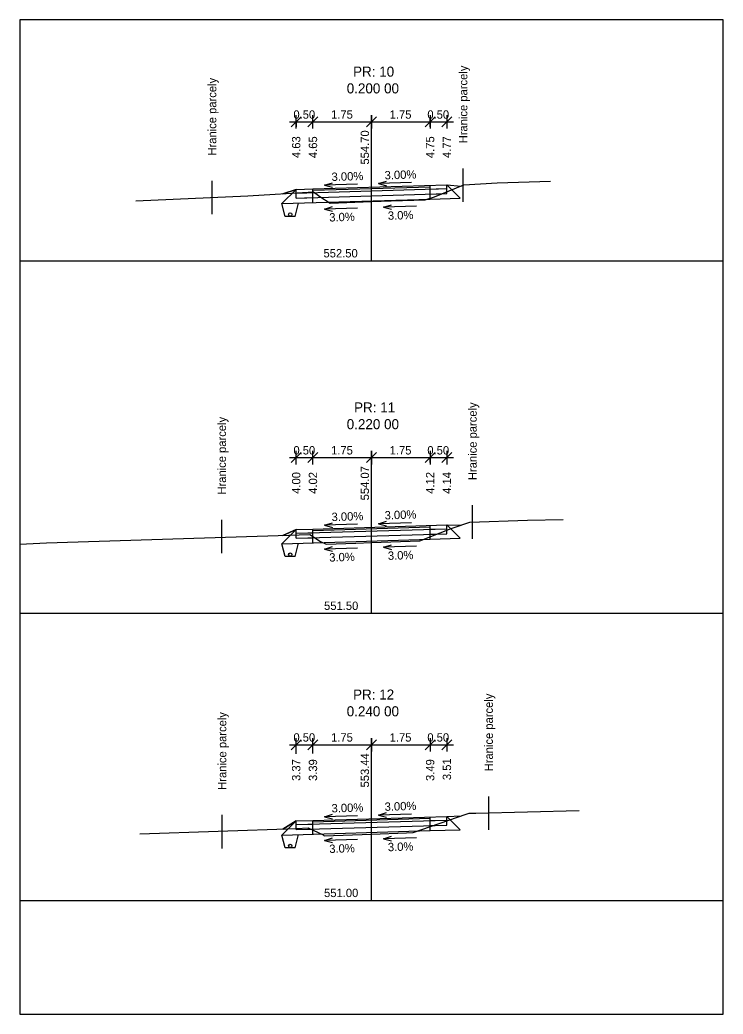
# Model space of a CAD drawing. Extents: x -603737 to -603383, y -1112154 to -1112124.
# Drawn here: x -603636.4 to -603615.4, y -1112153.84 to -1112124.14 of the extents above; entities that cross this region are included whole.
import ezdxf

# ---------------------------------------------------------------- set-up
doc = ezdxf.new("R2010")
doc.units = 0
for name, color, linetype in [('_křivky z hran', 7, 'Continuous'), ('_netisk', 7, 'Continuous'), ('C3D_Podsestava-Popis', 7, 'Continuous'), ('C3D_PP-Popisek', 7, 'Continuous'), ('C3D_PR', 7, 'Continuous'), ('C3D_ZPR', 7, 'Continuous'), ('Default', 7, 'Continuous'), ('konstrukce', 7, 'Continuous')]:
    doc.layers.add(name, color=color, linetype=linetype)

# ---------------------------------------------------------------- blocks, each defined once
blk = doc.blocks.new('_Oblique')
at = {"layer": 'Default'}
blk.add_line((-0.5, -0.5), (0.5, 0.5), dxfattribs=at)
blk = doc.blocks.new('AeccTickLine')
at = {"layer": 'Default'}
blk.add_line((0, 1), (0, -1), dxfattribs=at)

msp = doc.modelspace()

# ---------------------------------------------------------------- linework, layer by layer
at = {"layer": '_netisk'}
msp.add_lwpolyline([(-603636.395, -1112153.84), (-603615.395, -1112153.84), (-603615.395, -1112124.14), (-603636.395, -1112124.14)], close=True, dxfattribs=at)
at = {"layer": 'C3D_Podsestava-Popis'}
for p, q in [((-603628.345, -1112127.186), (-603625.895, -1112127.186)), ((-603627.645, -1112127.336), (-603627.645, -1112127.191)), ((-603625.895, -1112127.336), (-603625.895, -1112127.138)), ((-603625.895, -1112127.186), (-603623.445, -1112127.186)), ((-603624.145, -1112127.336), (-603624.145, -1112127.086)), ((-603623.645, -1112127.071), (-603623.645, -1112127.336)), ((-603628.145, -1112127.206), (-603628.145, -1112127.336)), ((-603628.345, -1112137.217), (-603625.895, -1112137.217)), ((-603625.895, -1112137.217), (-603623.445, -1112137.217)), ((-603624.145, -1112137.367), (-603624.145, -1112137.244)), ((-603623.645, -1112137.229), (-603623.645, -1112137.367)), ((-603628.145, -1112137.364), (-603628.145, -1112137.367)), ((-603627.645, -1112137.367), (-603627.645, -1112137.349)), ((-603625.895, -1112137.367), (-603625.895, -1112137.297)), ((-603628.345, -1112145.794), (-603625.895, -1112145.794)), ((-603625.895, -1112145.794), (-603623.445, -1112145.794)), ((-603628.145, -1112146.069), (-603628.145, -1112145.944)), ((-603627.645, -1112146.054), (-603627.645, -1112145.944)), ((-603625.895, -1112146.001), (-603625.895, -1112145.944)), ((-603624.145, -1112145.949), (-603624.145, -1112145.944)), ((-603623.645, -1112145.934), (-603623.645, -1112145.944))]:
    msp.add_line(p, q, dxfattribs=at)
at = {"layer": 'C3D_PP-Popisek'}
for p, q in [((-603625.687, -1112129.032), (-603625.45, -1112128.956)), ((-603627.298, -1112129.08), (-603627.062, -1112129.005)), ((-603626.314, -1112129.051), (-603627.298, -1112129.08)), ((-603627.298, -1112129.08), (-603627.057, -1112129.141)), ((-603624.703, -1112129.002), (-603625.687, -1112129.032)), ((-603625.687, -1112129.032), (-603625.446, -1112129.093)), ((-603627.298, -1112129.79), (-603627.062, -1112129.715)), ((-603626.314, -1112129.761), (-603627.298, -1112129.79)), ((-603627.298, -1112129.79), (-603627.057, -1112129.851)), ((-603625.534, -1112129.737), (-603625.297, -1112129.662)), ((-603624.55, -1112129.708), (-603625.534, -1112129.737)), ((-603625.534, -1112129.737), (-603625.293, -1112129.799)), ((-603627.298, -1112139.239), (-603627.062, -1112139.163)), ((-603626.314, -1112139.209), (-603627.298, -1112139.239)), ((-603627.298, -1112139.239), (-603627.057, -1112139.3)), ((-603625.687, -1112139.19), (-603625.45, -1112139.115)), ((-603624.703, -1112139.161), (-603625.687, -1112139.19)), ((-603625.687, -1112139.19), (-603625.446, -1112139.251)), ((-603627.298, -1112139.949), (-603627.062, -1112139.873)), ((-603626.314, -1112139.919), (-603627.298, -1112139.949)), ((-603627.298, -1112139.949), (-603627.057, -1112140.01)), ((-603625.534, -1112139.896), (-603625.297, -1112139.82)), ((-603624.55, -1112139.866), (-603625.534, -1112139.896)), ((-603625.534, -1112139.896), (-603625.293, -1112139.957)), ((-603627.298, -1112147.943), (-603627.062, -1112147.868)), ((-603626.314, -1112147.914), (-603627.298, -1112147.943)), ((-603627.298, -1112147.943), (-603627.057, -1112148.004)), ((-603625.687, -1112147.895), (-603625.45, -1112147.819)), ((-603624.703, -1112147.865), (-603625.687, -1112147.895)), ((-603625.687, -1112147.895), (-603625.446, -1112147.956)), ((-603625.534, -1112148.601), (-603625.297, -1112148.525)), ((-603624.55, -1112148.571), (-603625.534, -1112148.601)), ((-603627.298, -1112148.654), (-603627.062, -1112148.578)), ((-603626.314, -1112148.624), (-603627.298, -1112148.654)), ((-603627.298, -1112148.654), (-603627.057, -1112148.715)), ((-603625.534, -1112148.601), (-603625.293, -1112148.662))]:
    msp.add_line(p, q, dxfattribs=at)
at = {"layer": 'C3D_PR'}
for points in [[(-603632.933, -1112129.543), (-603629.584, -1112129.397), (-603627.629, -1112129.279), (-603627.434, -1112129.413), (-603627.125, -1112129.613), (-603625.895, -1112129.57), (-603625.307, -1112129.55), (-603624.296, -1112129.511), (-603624.013, -1112129.422), (-603623.14, -1112129.071), (-603622.14, -1112129.009), (-603620.554, -1112128.961)], [(-603636.395, -1112139.8), (-603635.601, -1112139.765), (-603627.74, -1112139.516), (-603627.415, -1112139.725), (-603627.253, -1112139.802), (-603626.367, -1112139.77), (-603625.895, -1112139.754), (-603624.452, -1112139.705), (-603623.519, -1112139.333), (-603622.96, -1112139.14), (-603621.233, -1112139.089), (-603620.17, -1112139.064)], [(-603632.813, -1112148.457), (-603628.138, -1112148.299), (-603627.79, -1112148.274), (-603627.339, -1112148.489), (-603627.309, -1112148.515), (-603625.895, -1112148.462), (-603624.852, -1112148.424), (-603624.651, -1112148.41), (-603623.065, -1112147.864), (-603622.976, -1112147.833), (-603622.78, -1112147.833), (-603619.689, -1112147.759)]]:
    msp.add_lwpolyline(points, dxfattribs=at)
at = {"layer": 'C3D_ZPR'}
for p, q in [((-603625.895, -1112131.336), (-603625.895, -1112127.336)), ((-603623.157, -1112129.578), (-603623.157, -1112128.578)), ((-603630.655, -1112129.944), (-603630.655, -1112128.944)), ((-603628.568, -1112129.628), (-603628.145, -1112129.206)), ((-603628.145, -1112129.206), (-603628.54, -1112129.334)), ((-603628.54, -1112129.334), (-603628.145, -1112129.206)), ((-603628.145, -1112129.316), (-603623.645, -1112129.181)), ((-603628.145, -1112129.206), (-603627.645, -1112129.191)), ((-603628.145, -1112129.466), (-603628.145, -1112129.206)), ((-603628.145, -1112129.466), (-603628.145, -1112129.206)), ((-603627.645, -1112129.191), (-603623.645, -1112129.071)), ((-603627.645, -1112129.231), (-603624.145, -1112129.126)), ((-603627.645, -1112129.601), (-603627.645, -1112129.191)), ((-603627.645, -1112129.301), (-603627.645, -1112129.231)), ((-603624.145, -1112129.126), (-603624.145, -1112129.086)), ((-603624.145, -1112129.496), (-603624.145, -1112129.086)), ((-603624.145, -1112129.196), (-603623.645, -1112129.181)), ((-603624.145, -1112129.346), (-603624.145, -1112129.196)), ((-603623.645, -1112129.331), (-603623.645, -1112129.071)), ((-603623.645, -1112129.331), (-603623.645, -1112129.071)), ((-603623.645, -1112129.071), (-603623.247, -1112129.469)), ((-603623.645, -1112129.071), (-603623.22, -1112129.103)), ((-603623.645, -1112129.071), (-603623.22, -1112129.103)), ((-603628.568, -1112129.628), (-603624.145, -1112129.496)), ((-603628.145, -1112129.316), (-603627.645, -1112129.301)), ((-603628.145, -1112129.466), (-603623.645, -1112129.331)), ((-603628.145, -1112129.466), (-603627.645, -1112129.451)), ((-603627.645, -1112129.601), (-603627.645, -1112129.451)), ((-603624.145, -1112129.346), (-603623.645, -1112129.331)), ((-603624.145, -1112129.496), (-603623.247, -1112129.469)), ((-603636.395, -1112131.336), (-603615.395, -1112131.336)), ((-603625.895, -1112141.867), (-603625.895, -1112137.367)), ((-603622.878, -1112139.638), (-603622.878, -1112138.638)), ((-603630.365, -1112140.071), (-603630.365, -1112139.071)), ((-603628.568, -1112139.787), (-603628.145, -1112139.364)), ((-603628.145, -1112139.364), (-603628.54, -1112139.541)), ((-603628.54, -1112139.541), (-603628.145, -1112139.364)), ((-603628.145, -1112139.474), (-603623.645, -1112139.339)), ((-603628.145, -1112139.364), (-603627.645, -1112139.349)), ((-603628.145, -1112139.624), (-603628.145, -1112139.364)), ((-603628.145, -1112139.624), (-603628.145, -1112139.364)), ((-603627.645, -1112139.349), (-603623.645, -1112139.229)), ((-603627.645, -1112139.389), (-603624.145, -1112139.284)), ((-603627.645, -1112139.759), (-603627.645, -1112139.349)), ((-603624.145, -1112139.284), (-603624.145, -1112139.244)), ((-603624.145, -1112139.654), (-603624.145, -1112139.244)), ((-603624.145, -1112139.354), (-603623.645, -1112139.339)), ((-603624.145, -1112139.504), (-603624.145, -1112139.354)), ((-603623.645, -1112139.489), (-603623.645, -1112139.229)), ((-603623.645, -1112139.489), (-603623.645, -1112139.229)), ((-603623.645, -1112139.229), (-603623.247, -1112139.627)), ((-603623.645, -1112139.229), (-603623.22, -1112139.23)), ((-603623.645, -1112139.229), (-603623.22, -1112139.23)), ((-603628.568, -1112139.787), (-603624.145, -1112139.654)), ((-603628.145, -1112139.474), (-603627.645, -1112139.459)), ((-603628.145, -1112139.624), (-603623.645, -1112139.489)), ((-603628.145, -1112139.624), (-603627.645, -1112139.609)), ((-603627.645, -1112139.459), (-603627.645, -1112139.389)), ((-603627.645, -1112139.759), (-603627.645, -1112139.609)), ((-603624.145, -1112139.504), (-603623.645, -1112139.489)), ((-603624.145, -1112139.654), (-603623.247, -1112139.627)), ((-603636.395, -1112141.867), (-603615.395, -1112141.867)), ((-603625.895, -1112150.444), (-603625.895, -1112145.944)), ((-603622.395, -1112148.338), (-603622.395, -1112147.338)), ((-603630.356, -1112148.89), (-603630.356, -1112147.89)), ((-603627.645, -1112148.054), (-603623.645, -1112147.934)), ((-603624.145, -1112147.989), (-603624.145, -1112147.949)), ((-603624.145, -1112148.359), (-603624.145, -1112147.949)), ((-603623.645, -1112147.934), (-603623.22, -1112147.917)), ((-603623.645, -1112147.934), (-603623.22, -1112147.917)), ((-603623.645, -1112148.194), (-603623.645, -1112147.934)), ((-603623.645, -1112148.194), (-603623.645, -1112147.934)), ((-603623.247, -1112148.332), (-603623.645, -1112147.934)), ((-603628.568, -1112148.492), (-603628.145, -1112148.069)), ((-603628.145, -1112148.069), (-603628.54, -1112148.313)), ((-603628.54, -1112148.313), (-603628.145, -1112148.069)), ((-603628.145, -1112148.179), (-603623.645, -1112148.044)), ((-603628.145, -1112148.069), (-603627.645, -1112148.054)), ((-603628.145, -1112148.329), (-603628.145, -1112148.069)), ((-603628.145, -1112148.329), (-603628.145, -1112148.069)), ((-603628.145, -1112148.179), (-603627.645, -1112148.164)), ((-603628.145, -1112148.329), (-603623.645, -1112148.194)), ((-603627.645, -1112148.094), (-603624.145, -1112147.989)), ((-603627.645, -1112148.464), (-603627.645, -1112148.054)), ((-603627.645, -1112148.164), (-603627.645, -1112148.094)), ((-603624.145, -1112148.059), (-603623.645, -1112148.044)), ((-603624.145, -1112148.209), (-603624.145, -1112148.059)), ((-603624.145, -1112148.209), (-603623.645, -1112148.194)), ((-603628.568, -1112148.492), (-603624.145, -1112148.359)), ((-603628.145, -1112148.329), (-603627.645, -1112148.314)), ((-603627.645, -1112148.464), (-603627.645, -1112148.314)), ((-603624.145, -1112148.359), (-603623.247, -1112148.332)), ((-603636.395, -1112150.444), (-603615.395, -1112150.444))]:
    msp.add_line(p, q, dxfattribs=at)
at = {"layer": 'konstrukce'}
for p, q in [((-603628.472, -1112130.014), (-603628.568, -1112129.628)), ((-603628.172, -1112130.014), (-603628.072, -1112129.614)), ((-603628.172, -1112130.014), (-603628.472, -1112130.014)), ((-603628.472, -1112140.172), (-603628.568, -1112139.787)), ((-603628.172, -1112140.172), (-603628.072, -1112139.772)), ((-603628.172, -1112140.172), (-603628.472, -1112140.172)), ((-603628.472, -1112148.877), (-603628.568, -1112148.492)), ((-603628.172, -1112148.877), (-603628.072, -1112148.477)), ((-603628.172, -1112148.877), (-603628.472, -1112148.877))]:
    msp.add_line(p, q, dxfattribs=at)
for centre in [(-603628.322, -1112129.954), (-603628.322, -1112140.112), (-603628.322, -1112148.817)]:
    msp.add_circle(centre, 0.05, dxfattribs=at)

# ---------------------------------------------------------------- block references
at = {"layer": '_křivky z hran', "rotation": 180}
for name, p, xscale, yscale in [('_Oblique', (-603628.145, -1112127.186), 0.3, 0.3), ('AeccTickLine', (-603628.145, -1112127.186), 0.2, 0.20000000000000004), ('_Oblique', (-603627.645, -1112127.186), 0.3, 0.3), ('AeccTickLine', (-603627.645, -1112127.186), 0.2, 0.20000000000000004), ('_Oblique', (-603625.895, -1112127.186), 0.3, 0.3), ('AeccTickLine', (-603625.895, -1112127.186), 0.2, 0.20000000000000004), ('_Oblique', (-603628.145, -1112137.217), 0.3, 0.3), ('AeccTickLine', (-603628.145, -1112137.217), 0.2, 0.20000000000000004), ('_Oblique', (-603627.645, -1112137.217), 0.3, 0.3), ('AeccTickLine', (-603627.645, -1112137.217), 0.2, 0.20000000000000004), ('_Oblique', (-603625.895, -1112137.217), 0.3, 0.3), ('AeccTickLine', (-603625.895, -1112137.217), 0.2, 0.20000000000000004), ('AeccTickLine', (-603628.145, -1112145.794), 0.2, 0.20000000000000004), ('AeccTickLine', (-603627.645, -1112145.794), 0.2, 0.20000000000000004), ('AeccTickLine', (-603625.895, -1112145.794), 0.2, 0.20000000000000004), ('_Oblique', (-603628.145, -1112145.794), 0.3, 0.3), ('_Oblique', (-603627.645, -1112145.794), 0.3, 0.3), ('_Oblique', (-603625.895, -1112145.794), 0.3, 0.3)]:
    msp.add_blockref(name, p, dxfattribs=dict(at, xscale=xscale, yscale=yscale))
at = {"layer": '_křivky z hran'}
for name, p, xscale, yscale in [('_Oblique', (-603625.895, -1112127.186), 0.3, 0.3), ('AeccTickLine', (-603625.895, -1112127.186), 0.2, 0.20000000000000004), ('_Oblique', (-603624.145, -1112127.186), 0.3, 0.3), ('AeccTickLine', (-603624.145, -1112127.186), 0.2, 0.20000000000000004), ('_Oblique', (-603623.645, -1112127.186), 0.3, 0.3), ('AeccTickLine', (-603623.645, -1112127.186), 0.2, 0.20000000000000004), ('_Oblique', (-603625.895, -1112137.217), 0.3, 0.3), ('AeccTickLine', (-603625.895, -1112137.217), 0.2, 0.20000000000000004), ('_Oblique', (-603624.145, -1112137.217), 0.3, 0.3), ('AeccTickLine', (-603624.145, -1112137.217), 0.2, 0.20000000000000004), ('_Oblique', (-603623.645, -1112137.217), 0.3, 0.3), ('AeccTickLine', (-603623.645, -1112137.217), 0.2, 0.20000000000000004), ('AeccTickLine', (-603625.895, -1112145.794), 0.2, 0.20000000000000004), ('AeccTickLine', (-603624.145, -1112145.794), 0.2, 0.20000000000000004), ('AeccTickLine', (-603623.645, -1112145.794), 0.2, 0.20000000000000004), ('_Oblique', (-603625.895, -1112145.794), 0.3, 0.3), ('_Oblique', (-603624.145, -1112145.794), 0.3, 0.3), ('_Oblique', (-603623.645, -1112145.794), 0.3, 0.3)]:
    msp.add_blockref(name, p, dxfattribs=dict(at, xscale=xscale, yscale=yscale))

# ---------------------------------------------------------------- texts
at = {"layer": 'C3D_Podsestava-Popis'}
for s, rotation, p in [('0.50', 360, (-603628.227, -1112127.092)), ('1.75', 360, (-603627.103, -1112127.092)), ('1.75', 360, (-603627.103, -1112127.092)), ('1.75', 360, (-603625.353, -1112127.092)), ('1.75', 360, (-603625.353, -1112127.092)), ('0.50', 360, (-603624.227, -1112127.092)), ('554.70', 90, (-603625.969, -1112128.462)), ('4.63', 90, (-603628.019, -1112128.268)), ('4.63', 90, (-603628.019, -1112128.268)), ('4.65', 90, (-603627.519, -1112128.269)), ('4.75', 90, (-603624.02, -1112128.269)), ('4.77', 90, (-603623.52, -1112128.268)), ('4.77', 90, (-603623.52, -1112128.268)), ('3.00%', 1.7184, (-603625.5, -1112128.906)), ('3.00%', 1.7184, (-603627.085, -1112128.954)), ('3.0%', 1.7184, (-603625.403, -1112130.113)), ('3.0%', 1.7184, (-603627.153, -1112130.165)), ('0.50', 360, (-603628.227, -1112137.123)), ('1.75', 360, (-603627.103, -1112137.123)), ('1.75', 360, (-603627.103, -1112137.123)), ('1.75', 360, (-603625.353, -1112137.123)), ('1.75', 360, (-603625.353, -1112137.123)), ('0.50', 360, (-603624.227, -1112137.123)), ('554.07', 90, (-603625.969, -1112138.493)), ('4.00', 90, (-603628.019, -1112138.298)), ('4.00', 90, (-603628.019, -1112138.298)), ('4.02', 90, (-603627.519, -1112138.297)), ('4.12', 90, (-603624.019, -1112138.297)), ('4.14', 90, (-603623.519, -1112138.298)), ('4.14', 90, (-603623.519, -1112138.298)), ('3.00%', 1.7184, (-603627.085, -1112139.113)), ('3.00%', 1.7184, (-603625.5, -1112139.064)), ('3.0%', 1.7184, (-603627.153, -1112140.324)), ('3.0%', 1.7184, (-603625.403, -1112140.271)), ('0.50', 360, (-603628.227, -1112145.7)), ('1.75', 360, (-603627.103, -1112145.7)), ('1.75', 360, (-603627.103, -1112145.7)), ('1.75', 360, (-603625.353, -1112145.7)), ('1.75', 360, (-603625.353, -1112145.7)), ('0.50', 360, (-603624.227, -1112145.7)), ('553.44', 90, (-603625.969, -1112147.069)), ('3.37', 90, (-603628.019, -1112146.875)), ('3.37', 90, (-603628.019, -1112146.875)), ('3.39', 90, (-603627.519, -1112146.876)), ('3.49', 90, (-603624.019, -1112146.876)), ('3.51', 90, (-603623.519, -1112146.851)), ('3.51', 90, (-603623.519, -1112146.851)), ('3.00%', 1.7184, (-603627.085, -1112147.817)), ('3.00%', 1.7184, (-603625.5, -1112147.769)), ('3.0%', 1.7184, (-603627.153, -1112149.028)), ('3.0%', 1.7184, (-603625.403, -1112148.976))]:
    msp.add_text(s, height=0.25, rotation=rotation, dxfattribs=at).set_placement(p)
at = {"layer": 'C3D_ZPR'}
for s, p in [('PR: 10', (-603626.445, -1112125.836)), ('0.200 00', (-603626.635, -1112126.336)), ('PR: 11', (-603626.415, -1112135.867)), ('0.220 00', (-603626.635, -1112136.367)), ('PR: 12', (-603626.445, -1112144.444)), ('0.240 00', (-603626.635, -1112144.944))]:
    msp.add_text(s, height=0.3, dxfattribs=at).set_placement(p)
for s, rotation, p in [('Hranice parcely', 90, (-603623.032, -1112127.828)), ('Hranice parcely', 90, (-603630.53, -1112128.194)), ('552.50', 360, (-603627.329, -1112131.236)), ('Hranice parcely', 90, (-603622.753, -1112137.888)), ('Hranice parcely', 90, (-603630.24, -1112138.321)), ('551.50', 360, (-603627.312, -1112141.767)), ('Hranice parcely', 90, (-603622.27, -1112146.588)), ('Hranice parcely', 90, (-603630.231, -1112147.14)), ('551.00', 360, (-603627.312, -1112150.344))]:
    msp.add_text(s, height=0.25, rotation=rotation, dxfattribs=at).set_placement(p)

doc.saveas('drawing.dxf')
